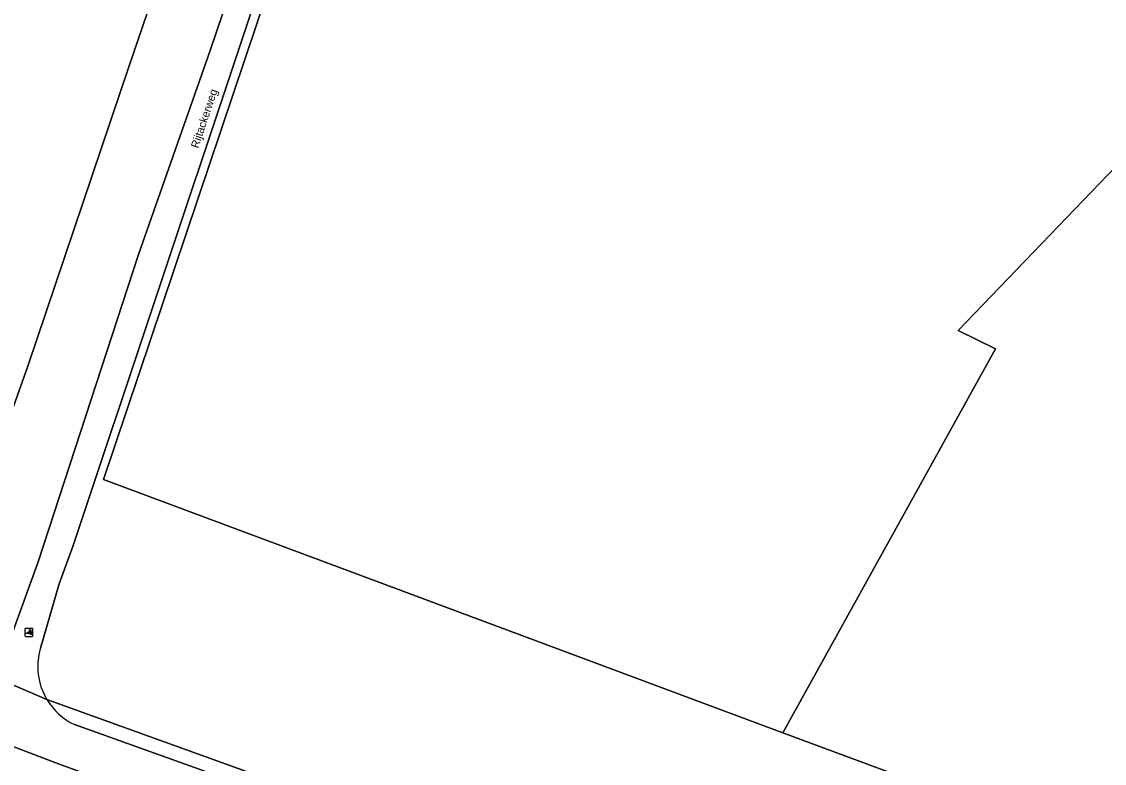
# Model space of a CAD drawing. Extents: x 156061 to 157804, y 383437 to 385640.
# Drawn here: x 156563.1 to 156698.4, y 385081.3 to 385173.9 of the extents above; entities that cross this region are included whole.
import ezdxf

# ---------------------------------------------------------------- set-up
doc = ezdxf.new("R2010")
doc.units = 0
for name, color, linetype in [('IMGEO_Erf', 7, 'Continuous'), ('IMGEO_Groenvoorziening', 7, 'Continuous'), ('IMGEO_Hek', 7, 'Continuous'), ('IMGEO_Openbare_ruimte_label', 7, 'Continuous'), ('IMGEO_Poller', 7, 'Continuous'), ('IMGEO_Rijbaan_lokaal_gesloten', 7, 'Continuous')]:
    doc.layers.add(name, color=color, linetype=linetype)

msp = doc.modelspace()

# ---------------------------------------------------------------- linework, layer by layer
at = {"layer": 'IMGEO_Erf'}
msp.add_lwpolyline([(156729.5, 385186.7), (156715.5, 385172.11), (156680.12, 385135.3), (156684.8, 385133.04), (156658.24, 385085.09), (156712.13, 385065.11), (156712.19, 385065.09), (156712.02, 385064.64), (156712.96, 385064.3), (156713.14, 385064.81), (156713.45, 385064.69), (156717.68, 385063.12), (156717.97, 385063.01), (156717.78, 385062.51), (156718.7, 385062.16), (156718.88, 385062.65), (156870.37, 385006.51), (156870.97, 385006.29), (156875.12, 385016.62), (156892.55, 385064.29), (156865.99, 385088.29), (156852.11, 385101.79), (156804.77, 385147.48), (156780.44, 385174.16)], dxfattribs=at)
at = {"layer": 'IMGEO_Groenvoorziening'}
for points in [[(156707.04, 385047.11), (156708.32, 385050.62), (156713.45, 385064.69), (156713.14, 385064.81), (156712.96, 385064.3), (156712.02, 385064.64), (156712.19, 385065.09), (156712.13, 385065.11), (156658.24, 385085.09), (156573.38, 385116.71), (156605.74, 385212.86), (156607.97, 385218.58), (156610.73, 385223.59), (156612.43, 385226.05), (156614.37, 385228.41), (156616.52, 385230.47), (156619.08, 385232.21), (156621.74, 385233.41), (156624.7, 385234.46), (156627.7, 385235.07), (156633.77, 385235.98), (156633.51, 385237.04), (156622.49, 385234.27)], [(156608.5, 385221.91), (156606.3, 385217.49), (156600.39, 385200.8), (156569.52, 385108.36), (156567.83, 385103.67), (156565.49, 385095.64)], [(156585.87, 385195.59), (156576.52, 385168.23), (156563.92, 385130.88), (156553.4, 385101.35), (156562.24, 385098.26), (156565.2, 385106.42), (156577.76, 385144.83), (156586.71, 385170.27), (156596.08, 385197.94)], [(156327.27, 385181.21), (156500, 385119), (156514.99, 385113.6), (156543.55, 385103.32), (156544.01, 385104.64), (156544.92, 385107.25), (156549.72, 385105.57), (156550.57, 385105.27), (156549.65, 385102.67), (156553.4, 385101.35), (156563.92, 385130.88), (156576.52, 385168.23), (156585.87, 385195.59)], [(156590.93, 385073.63), (156578.06, 385077.45), (156567.97, 385081.12), (156557.53, 385085.07), (156500, 385105.74), (156431.78, 385130.12), (156326.22, 385167.86), (156324.12, 385168.82), (156320.16, 385170.64)], [(156695.72, 385041.75), (156689.55, 385043.91), (156629.6, 385066.07), (156629.79, 385066.73), (156607.49, 385074.38), (156566.3, 385089.23)], [(156566.3, 385089.23), (156607.49, 385074.38), (156629.79, 385066.73), (156630.02, 385067.53), (156690.52, 385044.95), (156696.35, 385043.19)], [(156569.75, 385086.11), (156604.14, 385073.81), (156606.92, 385072.81), (156634.59, 385062.86), (156662.26, 385052.85), (156695.62, 385040.8)]]:
    msp.add_lwpolyline(points, dxfattribs=at)
msp.add_lwpolyline([(156684.8, 385133.04), (156680.12, 385135.3), (156715.5, 385172.11), (156729.5, 385186.7), (156743.63, 385201.6), (156639.59, 385234.27), (156633.77, 385235.98), (156627.7, 385235.07), (156624.7, 385234.46), (156621.74, 385233.41), (156619.08, 385232.21), (156616.52, 385230.47), (156614.37, 385228.41), (156612.43, 385226.05), (156610.73, 385223.59), (156607.97, 385218.58), (156605.74, 385212.86), (156573.38, 385116.71), (156658.24, 385085.09)], close=True, dxfattribs=at)
for centre, radius, start, end in [((156573.15, 385093.35), 7.99, 163.3523, 211.0386), ((156573.14, 385093.34), 7.98, 211.0034, 244.8903)]:
    msp.add_arc(centre, radius, start, end, dxfattribs=at)
at = {"layer": 'IMGEO_Hek'}
for points in [[(156658.24, 385085.09), (156573.38, 385116.71), (156605.74, 385212.86), (156607.97, 385218.58), (156610.73, 385223.59), (156612.43, 385226.05), (156614.37, 385228.41), (156616.52, 385230.47), (156619.08, 385232.21), (156621.74, 385233.41), (156624.7, 385234.46), (156627.7, 385235.07), (156633.77, 385235.98)], [(156715.5, 385172.11), (156680.12, 385135.3), (156684.8, 385133.04), (156658.24, 385085.09)], [(156658.24, 385085.09), (156712.13, 385065.11), (156712.19, 385065.09)]]:
    msp.add_lwpolyline(points, dxfattribs=at)
at = {"layer": 'IMGEO_Poller'}
for p, q in [((156563.56, 385098.02), (156563.56, 385097.22)), ((156563.56, 385098.02), (156563.56, 385097.22)), ((156564.46, 385098.12), (156563.65, 385098.12)), ((156564.46, 385098.12), (156563.65, 385098.12)), ((156564.55, 385097.22), (156564.55, 385098.02)), ((156564.55, 385097.22), (156564.55, 385098.02)), ((156563.65, 385097.12), (156564.46, 385097.12)), ((156563.65, 385097.12), (156564.46, 385097.12))]:
    msp.add_line(p, q, dxfattribs=at)
for points in [[(156564.19, 385097.48), (156563.68, 385097.48), (156564.11, 385097.75)], [(156564.23, 385097.85), (156564.22, 385097.78), (156564.1, 385097.98)], [(156564.1, 385097.98), (156564.33, 385097.91), (156564.26, 385097.88)], [(156564.25, 385097.3), (156564.32, 385097.53), (156564.35, 385097.47)], [(156564.38, 385097.44), (156564.46, 385097.43), (156564.25, 385097.3)]]:
    msp.add_lwpolyline(points, dxfattribs=at)
for centre, radius, start, end in [((156563.65, 385098.02), 0.0946, 90, 180), ((156563.65, 385098.02), 0.0946, 90, 180), ((156563.86, 385097.53), 0.332, 351.3247, 42.4854), ((156563.88, 385097.53), 0.476, 351.7527, 41.1691), ((156563.88, 385097.53), 0.516, 349.3569, 42.2912), ((156564.46, 385098.02), 0.0946, 0, 90), ((156564.46, 385098.02), 0.0946, 0, 90), ((156563.65, 385097.22), 0.0946, 180, 270), ((156563.65, 385097.22), 0.0946, 180, 270), ((156564.46, 385097.22), 0.0946, 270, 0), ((156564.46, 385097.22), 0.0946, 270, 0)]:
    msp.add_arc(centre, radius, start, end, dxfattribs=at)
at = {"layer": 'IMGEO_Rijbaan_lokaal_gesloten'}
for points in [[(156565.49, 385095.64), (156567.83, 385103.67), (156569.52, 385108.36), (156600.39, 385200.8), (156606.3, 385217.49), (156608.5, 385221.91)], [(156602.54, 385217.74), (156601.08, 385213.63), (156596.08, 385197.94), (156586.71, 385170.27), (156577.76, 385144.83), (156565.2, 385106.42), (156562.24, 385098.26), (156561.42, 385096), (156559.95, 385091.94), (156566.3, 385089.23)], [(156337.29, 385169.36), (156325.8, 385173.38), (156324.12, 385168.82), (156326.22, 385167.86), (156431.78, 385130.12), (156500, 385105.74), (156557.53, 385085.07), (156567.97, 385081.12), (156578.06, 385077.45), (156590.93, 385073.63), (156601.32, 385070.53), (156604.14, 385073.81), (156569.75, 385086.11)], [(156566.3, 385089.23), (156559.95, 385091.94)]]:
    msp.add_lwpolyline(points, dxfattribs=at)
for centre, radius, start, end in [((156573.15, 385093.35), 7.99, 163.3523, 211.0386), ((156573.14, 385093.34), 7.98, 211.0034, 244.8903)]:
    msp.add_arc(centre, radius, start, end, dxfattribs=at)

# ---------------------------------------------------------------- texts
at = {"layer": 'IMGEO_Openbare_ruimte_label'}
msp.add_text('Rijtackerweg', height=1, rotation=71.5107, dxfattribs=at).set_placement((156585.2, 385158.01))

doc.saveas('drawing.dxf')
